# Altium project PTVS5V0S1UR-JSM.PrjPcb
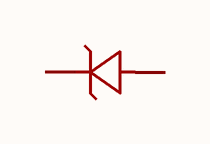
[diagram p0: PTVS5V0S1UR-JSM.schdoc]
1 sheet, 1 parts. Net scope: global (net labels, ports and power ports of the same name join across sheets).

## Sheet PTVS5V0S1UR-JSM.schdoc
size 127 x 101 mm

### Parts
D?  ptvs5v0s1ur-jsm  [SOD-123_L2.8-W1.8-LS3.7-RD]  (value not drawn)

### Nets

Not connected (* = marked no-connect by the designer): D? 1(C) 2(A)

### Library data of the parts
D? = ptvs5v0s1ur-jsm: 极性:单向;反向截止电压(Vrwm):5V;钳位电压:9.2V;峰值脉冲电流(Ipp):43.6A;峰值脉冲功率(Ppp):400W@10/1000us;击穿电压(VBR):7V;; Manufacturer: JSMSEMI(杰盛微); AddInBom: yes; ModelId: 7884390a25fb4c08947731ebfba7e3f8; ModelTransform: 144.8816,62.992,0,0,0,0,0,0,0; Polarity: 单向; Reverse Stand-Off Voltage (Vrwm): 5V; Clamping Voltage: 9.2V; Peak Pulse Current (Ipp): 43.6A; Voltage - Breakdown: 7V; Reverse Leakage Current (Ir): 500uA; Number of Channels: 单路; level of protection: IEC 61000-4-2; Type: TVS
